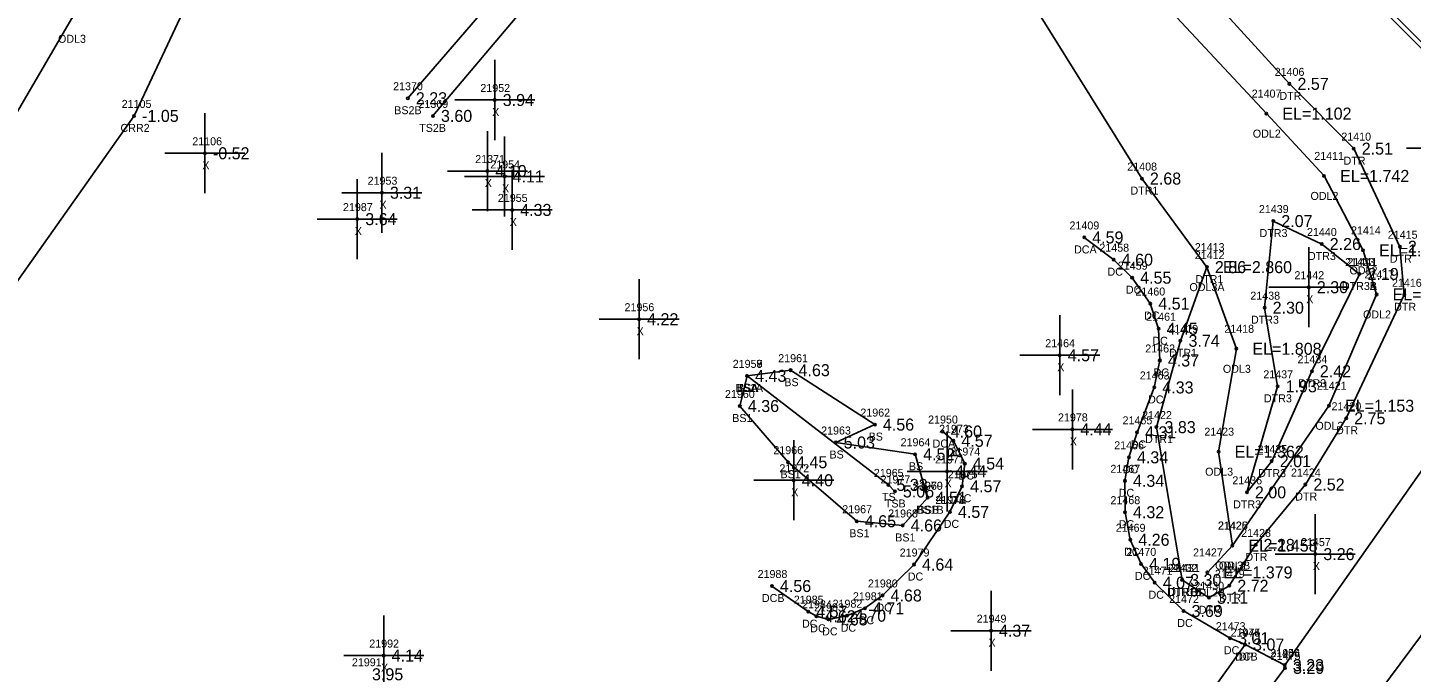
# Model space of a CAD drawing. Extents: x 2608745 to 2610333, y 641917 to 643463.
# Drawn here: x 2609885.8 to 2610058.8, y 642076.5 to 642157.1 of the extents above; entities that cross this region are included whole.
import ezdxf

# ---------------------------------------------------------------- set-up
doc = ezdxf.new("R2010")
doc.units = 0
for name, color, linetype in [('RD_DTM_BkLn1', 7, 'Continuous'), ('RD_DTM_BkLn2', 7, 'Continuous'), ('RD_DTM_BkLn_txCode', 7, 'Continuous'), ('RD_EX_Conc', 7, 'Continuous'), ('RD_EX_Conc_txCode', 7, 'Continuous'), ('RD_EX_Driveway', 7, 'Continuous'), ('RD_EX_Driveway_txCode', 7, 'Continuous'), ('RD_EX_H2O', 7, 'Continuous'), ('RD_EX_H2O_txCode', 7, 'Continuous'), ('RD_EX_Misc', 7, 'Continuous'), ('RD_EX_Misc_txCode', 7, 'Continuous'), ('RD_EX_Road', 7, 'Continuous'), ('RD_EX_Road_txCode', 7, 'Continuous'), ('RD_EX_TX_Conc_ELEV', 7, 'Continuous'), ('RD_EX_TX_Driveway_ELEV', 7, 'Continuous'), ('RD_EX_TX_H2O_ELEV', 7, 'Continuous'), ('RD_EX_TX_Misc_ELEV', 7, 'Continuous'), ('RD_EX_TX_Road_ELEV', 7, 'Continuous'), ('RD_SMD_Locator', 7, 'Continuous')]:
    doc.layers.add(name, color=color, linetype=linetype)

msp = doc.modelspace()

# ---------------------------------------------------------------- linework, layer by layer
at = {"layer": 'RD_DTM_BkLn1'}
for points in [[(2609991.14, 642222.22), (2610004.52, 642209.47), (2610026.41, 642188.23), (2610060.62, 642153.9), (2610064.44, 642147.89), (2610069, 642144.94), (2610070.6, 642141.24), (2610070.91, 642133.58), (2610072.62, 642129.27)], [(2610092.08, 642124.26), (2610033.92, 642046.06), (2609975.15, 641967.52)]]:
    msp.add_lwpolyline(points, dxfattribs=at)
at = {"layer": 'RD_DTM_BkLn2'}
for points in [[(2609957.67, 642238.22), (2609985.77, 642215.29), (2609991.2, 642207.2), (2609988.28, 642202.04), (2609982.8, 642193.37), (2609979.92, 642194.31), (2609971.84, 642180.1), (2609960.45, 642174.49), (2609936.49, 642146.07)], [(2609985.47, 642202.04), (2609967.41, 642183.84), (2609958.63, 642177.64), (2609933.35, 642148.28)], [(2609975.75, 642113.58), (2609974.84, 642109.81), (2609980.87, 642102.79), (2609989.46, 642095.41), (2609995.2, 642094.88), (2609998.3, 642098.34)], [(2609975.75, 642113.58), (2609981.18, 642114.29), (2609991.72, 642107.49), (2609986.82, 642105.25), (2609996.75, 642103.78), (2609998.3, 642098.34)], [(2609975.75, 642113.58), (2609993.41, 642099.95), (2609994.22, 642099.13)]]:
    msp.add_lwpolyline(points, dxfattribs=at)
at = {"layer": 'RD_EX_Conc'}
for points in [[(2610017.88, 642130.88), (2610021.57, 642128.1), (2610023.87, 642125.85), (2610026.14, 642122.62), (2610027.17, 642119.47), (2610027.33, 642115.5), (2610026.64, 642112.13), (2610024.48, 642106.52), (2610023.47, 642103.4), (2610022.97, 642100.46), (2610022.98, 642096.54), (2610023.64, 642093.09), (2610024.99, 642090.08), (2610026.69, 642087.72), (2610030.29, 642084.19), (2610036.11, 642080.79), (2610037.98, 642080)], [(2610000.2, 642106.62), (2610001.53, 642105.46), (2610002.96, 642102.62), (2610002.62, 642099.78), (2610001.1, 642096.58), (2609996.61, 642090), (2609992.68, 642086.13), (2609990.48, 642084.53), (2609988.22, 642083.6), (2609985.91, 642083.14), (2609984.42, 642083.53), (2609983.39, 642084.11), (2609978.85, 642087.31)]]:
    msp.add_lwpolyline(points, dxfattribs=at)
at = {"layer": 'RD_EX_Driveway'}
msp.add_lwpolyline([(2610042.94, 642077.42), (2610037.98, 642080), (2610027.54, 642065.43), (2610017.89, 642052.74), (2610020.81, 642047.62)], dxfattribs=at)
at = {"layer": 'RD_EX_H2O'}
for points in [[(2609545.26, 642628.98), (2609557.91, 642602.6), (2609591.74, 642540.6), (2609658.48, 642494.06), (2609739.9, 642422.86), (2609760.07, 642378.85), (2609808.54, 642339.07), (2609896.37, 642269.89), (2609925.48, 642240.69), (2609915.11, 642188.91), (2609891.33, 642158.21), (2609835.84, 642063.03)], [(2610001.65, 642196), (2609997.03, 642195), (2609993.92, 642192.05), (2609993.23, 642189.36), (2610025.09, 642138.24), (2610033.21, 642127.17), (2610029.91, 642117.96), (2610026.91, 642107.17), (2610030.12, 642088.07)], [(2610001.65, 642196), (2610043.53, 642150.08), (2610051.56, 642141.98), (2610057.33, 642129.72), (2610057.88, 642123.71), (2610050.62, 642108.28), (2610045.52, 642100), (2610039.29, 642092.45), (2610036.01, 642087.34), (2610033.47, 642085.84), (2610030.12, 642088.07)], [(2609998.2, 642191.89), (2610040.64, 642146.36), (2610047.86, 642138.57), (2610052.73, 642129.26), (2610054.42, 642123.75), (2610048.47, 642109.84), (2610036.4, 642092.37), (2610033.27, 642089.01)], [(2609911.25, 642171.95), (2609899.14, 642146.07), (2609837.93, 642059.5)], [(2610052.28, 642126.31), (2610046.33, 642114.16), (2610041.32, 642102.92), (2610038.21, 642099.02), (2610042.05, 642112.27), (2610040.43, 642122.1), (2610041.51, 642132.93), (2610047.56, 642130.06), (2610052.28, 642126.31)], [(2610033.21, 642127.17), (2610036.9, 642116.96), (2610034.68, 642104.1), (2610036.4, 642092.37)]]:
    msp.add_lwpolyline(points, dxfattribs=at)
at = {"layer": 'RD_EX_Misc'}
for p, q in [((2609944.21, 642143.06), (2609944.21, 642153.06)), ((2609907.99, 642136.4), (2609907.99, 642146.4)), ((2609939.21, 642148.06), (2609949.21, 642148.06)), ((2609943.29, 642134.18), (2609943.29, 642144.18)), ((2609945.44, 642133.5), (2609945.44, 642143.5)), ((2609902.99, 642141.4), (2609912.99, 642141.4)), ((2609930.11, 642131.47), (2609930.11, 642141.47)), ((2610058.17, 642142.04), (2610068.17, 642142.04)), ((2609927.03, 642128.17), (2609927.03, 642138.17)), ((2609938.29, 642139.18), (2609948.29, 642139.18)), ((2609940.44, 642138.5), (2609950.44, 642138.5)), ((2609946.39, 642129.32), (2609946.39, 642139.32)), ((2609925.11, 642136.47), (2609935.11, 642136.47)), ((2609941.39, 642134.32), (2609951.39, 642134.32)), ((2609922.03, 642133.17), (2609932.03, 642133.17)), ((2610045.95, 642119.66), (2610045.95, 642129.66)), ((2609962.25, 642115.66), (2609962.25, 642125.66)), ((2610040.95, 642124.66), (2610050.95, 642124.66)), ((2609957.25, 642120.66), (2609967.25, 642120.66)), ((2610014.82, 642111.16), (2610014.82, 642121.16)), ((2610009.82, 642116.16), (2610019.82, 642116.16)), ((2610016.4, 642101.89), (2610016.4, 642111.89)), ((2610000.74, 642096.63), (2610000.74, 642106.63)), ((2610011.4, 642106.89), (2610021.4, 642106.89)), ((2609981.58, 642095.53), (2609981.58, 642105.53)), ((2609995.74, 642101.63), (2610005.74, 642101.63)), ((2609976.58, 642100.53), (2609986.58, 642100.53)), ((2610046.76, 642086.3), (2610046.76, 642096.3)), ((2610041.76, 642091.3), (2610051.76, 642091.3)), ((2610006.23, 642076.73), (2610006.23, 642086.73)), ((2609930.33, 642073.62), (2609930.33, 642083.62)), ((2610001.23, 642081.73), (2610011.23, 642081.73)), ((2609925.33, 642078.62), (2609935.33, 642078.62))]:
    msp.add_line(p, q, dxfattribs=at)
at = {"layer": 'RD_EX_Road'}
for points in [[(2609991.14, 642222.22), (2610004.6, 642209.66), (2610026.66, 642188.37), (2610066.82, 642148.56), (2610069.65, 642145.36), (2610071.05, 642141.53), (2610071.68, 642138.94), (2610071.34, 642133.72), (2610072.62, 642129.27)], [(2610073.96, 642143.05), (2610073.97, 642133.89), (2610072.62, 642129.27), (2610072.13, 642123.73), (2610071.19, 642117.59), (2610042.94, 642077.42), (2610042.98, 642077.08), (2610020.81, 642047.62), (2610010.68, 642034.57), (2609995.36, 642013.51), (2609993.98, 642012.16), (2609992.65, 642010.59), (2609982.73, 641996.33), (2609971.73, 641982.02), (2609971.56, 641981.9), (2609966, 641974.62)]]:
    msp.add_lwpolyline(points, dxfattribs=at)
at = {"layer": 'RD_SMD_Locator'}
for centre in [(2610043.53, 642150.08), (2609933.35, 642148.28), (2609944.21, 642148.06), (2610040.64, 642146.36), (2609899.14, 642146.07), (2609936.49, 642146.07), (2609907.99, 642141.4), (2610051.56, 642141.98), (2609943.29, 642139.18), (2609945.44, 642138.5), (2610025.09, 642138.24), (2610047.86, 642138.57), (2609930.11, 642136.47), (2609946.39, 642134.32), (2609927.03, 642133.17), (2610041.51, 642132.93), (2610017.88, 642130.88), (2610047.56, 642130.06), (2610052.73, 642129.26), (2610057.33, 642129.72), (2610021.57, 642128.1), (2610023.87, 642125.85), (2610033.21, 642127.17), (2610033.21, 642127.17), (2610052.28, 642126.31), (2610052.28, 642126.31), (2610045.95, 642124.66), (2610054.42, 642123.75), (2610026.14, 642122.62), (2610040.43, 642122.1), (2610057.88, 642123.71), (2609962.25, 642120.66), (2610027.17, 642119.47), (2610029.91, 642117.96), (2610036.9, 642116.96), (2610014.82, 642116.16), (2610027.33, 642115.5), (2609975.75, 642113.58), (2609975.75, 642113.58), (2609975.75, 642113.58), (2609981.18, 642114.29), (2610046.33, 642114.16), (2610026.64, 642112.13), (2610042.05, 642112.27), (2609974.84, 642109.81), (2610048.47, 642109.84), (2610050.62, 642108.28), (2609991.72, 642107.49), (2610000.2, 642106.62), (2610016.4, 642106.89), (2610024.48, 642106.52), (2610026.91, 642107.17), (2609986.82, 642105.25), (2610001.53, 642105.46), (2609996.75, 642103.78), (2610023.47, 642103.4), (2610034.68, 642104.1), (2609980.87, 642102.79), (2610000.74, 642101.63), (2610002.96, 642102.62), (2610041.32, 642102.92), (2609981.58, 642100.53), (2609993.41, 642099.95), (2610002.62, 642099.78), (2610022.97, 642100.46), (2610045.52, 642100), (2609994.22, 642099.13), (2609998.3, 642098.34), (2609998.3, 642098.34), (2610038.21, 642099.02), (2610001.1, 642096.58), (2610022.98, 642096.54), (2609989.46, 642095.41), (2609995.2, 642094.88), (2610023.64, 642093.09), (2610036.4, 642092.37), (2610036.4, 642092.37), (2610039.29, 642092.45), (2610046.76, 642091.3), (2609996.61, 642090), (2610024.99, 642090.08), (2610026.69, 642087.72), (2610030.12, 642088.07), (2610030.12, 642088.07), (2610033.27, 642089.01), (2609978.85, 642087.31), (2609992.68, 642086.13), (2610033.47, 642085.84), (2610036.01, 642087.34), (2609983.39, 642084.11), (2609990.48, 642084.53), (2610030.29, 642084.19), (2609984.42, 642083.53), (2609985.91, 642083.14), (2609988.22, 642083.6), (2610006.23, 642081.73), (2610036.11, 642080.79), (2610037.98, 642080), (2610037.98, 642080), (2609930.33, 642078.62), (2610042.94, 642077.42), (2610042.94, 642077.42), (2610042.98, 642077.08)]:
    msp.add_circle(centre, 0.15, dxfattribs=at)

# ---------------------------------------------------------------- texts
at = {"layer": 'RD_DTM_BkLn_txCode'}
for s, p in [('21370', (2609931.51, 642149.28)), ('BS2B', (2609931.65, 642146.28)), ('21369', (2609934.67, 642147.07)), ('TS2B', (2609934.77, 642144.07)), ('21957', (2609973.95, 642114.58)), ('21958', (2609973.95, 642114.58)), ('21959', (2609973.95, 642114.58)), ('21961', (2609979.64, 642115.29)), ('21960', (2609972.98, 642110.81)), ('BS1A', (2609974.31, 642111.58)), ('TSA', (2609974.46, 642111.58)), ('BSA', (2609974.48, 642111.58)), ('BS', (2609980.4, 642112.29)), ('BS1', (2609973.89, 642107.81)), ('21962', (2609989.9, 642108.49)), ('21963', (2609985, 642106.25)), ('BS', (2609990.94, 642105.49)), ('21964', (2609994.93, 642104.78)), ('21966', (2609979.03, 642103.79)), ('BS', (2609986.04, 642103.25)), ('BS1', (2609979.92, 642100.79)), ('21965', (2609991.59, 642100.95)), ('BS', (2609995.97, 642101.78)), ('21977', (2609992.43, 642100.13)), ('21970', (2609996.47, 642099.34)), ('21969', (2609996.49, 642099.34)), ('TS', (2609992.61, 642097.95)), ('TSB', (2609992.96, 642097.13)), ('21967', (2609987.64, 642096.41)), ('21968', (2609993.38, 642095.88)), ('BS1B', (2609996.89, 642096.34)), ('BSB', (2609997.05, 642096.34)), ('BS1', (2609988.52, 642093.41)), ('BS1', (2609994.26, 642092.88)), ('21991', (2609926.36, 642077.28))]:
    msp.add_text(s, height=1, dxfattribs=at).set_placement(p)
at = {"layer": 'RD_EX_Conc_txCode'}
for s, p in [('21409', (2610016.04, 642131.88)), ('DCA', (2610016.61, 642128.88)), ('21458', (2610019.77, 642129.1)), ('21459', (2610022.08, 642126.85)), ('DC', (2610020.79, 642126.1)), ('DC', (2610023.09, 642123.85)), ('21460', (2610024.28, 642123.62)), ('DC', (2610025.36, 642120.62)), ('21461', (2610025.63, 642120.47)), ('21462', (2610025.51, 642116.5)), ('DC', (2610026.39, 642117.47)), ('21463', (2610024.82, 642113.13)), ('DC', (2610026.55, 642113.5)), ('DC', (2610025.86, 642110.13)), ('21950', (2609998.37, 642107.62)), ('21465', (2610022.67, 642107.52)), ('21973', (2609999.74, 642106.46)), ('DCA', (2609998.93, 642104.62)), ('21466', (2610021.63, 642104.4)), ('DC', (2610023.7, 642104.52)), ('DC', (2610000.75, 642103.46)), ('21974', (2610001.16, 642103.62)), ('21975', (2610000.83, 642100.78)), ('DC', (2610002.18, 642100.62)), ('21467', (2610021.15, 642101.46)), ('DC', (2610022.69, 642101.4)), ('21976', (2609999.28, 642097.58)), ('DC', (2610001.84, 642097.78)), ('21468', (2610021.16, 642097.54)), ('DC', (2610022.19, 642098.46)), ('DC', (2610000.32, 642094.58)), ('21469', (2610021.82, 642094.09)), ('DC', (2610022.2, 642094.54)), ('21979', (2609994.82, 642091)), ('DC', (2610022.86, 642091.09)), ('21470', (2610023.16, 642091.08)), ('21988', (2609977.06, 642088.31)), ('21471', (2610025.18, 642088.72)), ('21980', (2609990.85, 642087.13)), ('DC', (2609995.83, 642088)), ('DC', (2610024.21, 642088.08)), ('DCB', (2609977.6, 642085.31)), ('21985', (2609981.59, 642085.11)), ('21981', (2609988.97, 642085.53)), ('DC', (2610025.91, 642085.72)), ('21472', (2610028.49, 642085.19)), ('21984', (2609982.62, 642084.53)), ('21983', (2609984.12, 642084.14)), ('21982', (2609986.43, 642084.6)), ('DC', (2609991.91, 642084.13)), ('DC', (2609982.61, 642082.11)), ('DC', (2609983.64, 642081.53)), ('DC', (2609987.44, 642081.6)), ('DC', (2609989.7, 642082.53)), ('DC', (2610029.51, 642082.19)), ('21473', (2610034.32, 642081.79)), ('DC', (2609985.13, 642081.14)), ('21474', (2610036.18, 642081)), ('DC', (2610035.33, 642078.79)), ('DCB', (2610036.73, 642078))]:
    msp.add_text(s, height=1, dxfattribs=at).set_placement(p)
at = {"layer": 'RD_EX_Driveway_txCode'}
for s, p in [('21945', (2610036.18, 642081)), ('DP', (2610037.2, 642078)), ('21944', (2610041.15, 642078.42))]:
    msp.add_text(s, height=1, dxfattribs=at).set_placement(p)
at = {"layer": 'RD_EX_H2O_txCode'}
for s, p in [('ODL3', (2609889.63, 642155.21)), ('21406', (2610041.68, 642151.08)), ('21407', (2610038.81, 642148.36)), ('DTR', (2610042.27, 642148.08)), ('21105', (2609897.59, 642147.07)), ('CRR2', (2609897.44, 642144.07)), ('ODL2', (2610038.95, 642143.36)), ('21410', (2610050.01, 642142.98)), ('21411', (2610046.63, 642140.57)), ('21408', (2610023.26, 642139.24)), ('DTR', (2610050.29, 642139.98)), ('DTR1', (2610023.66, 642136.24)), ('ODL2', (2610046.16, 642135.57)), ('21439', (2610039.71, 642133.93)), ('DTR3', (2610039.79, 642130.93)), ('21440', (2610045.72, 642131.06)), ('21414', (2610051.22, 642131.26)), ('21415', (2610055.82, 642130.72)), ('21413', (2610031.7, 642129.17)), ('21412', (2610031.7, 642128.17)), ('DTR3', (2610045.84, 642128.06)), ('21433', (2610050.49, 642127.31)), ('21441', (2610050.77, 642127.31)), ('DTR', (2610056.07, 642127.72)), ('DTR1', (2610031.77, 642125.17)), ('ODL2', (2610051.04, 642126.26)), ('21417', (2610052.9, 642125.75)), ('21416', (2610056.34, 642124.71)), ('ODL3A', (2610031.03, 642124.17)), ('21438', (2610038.64, 642123.1)), ('DTR3A', (2610050.08, 642124.31)), ('DTR3B', (2610050.09, 642124.31)), ('DTR', (2610056.61, 642121.71)), ('DTR3', (2610038.72, 642120.1)), ('ODL2', (2610052.72, 642120.75)), ('21419', (2610028.4, 642118.96)), ('21418', (2610035.39, 642118.96)), ('DTR1', (2610028.48, 642115.96)), ('21434', (2610044.54, 642115.16)), ('ODL3', (2610035.21, 642113.96)), ('21437', (2610040.26, 642113.27)), ('DTR3', (2610044.62, 642112.16)), ('21421', (2610046.95, 642111.84)), ('DTR3', (2610040.34, 642110.27)), ('21420', (2610048.79, 642109.28)), ('21422', (2610025.12, 642108.17)), ('21423', (2610032.89, 642106.1)), ('ODL2', (2610046.77, 642106.84)), ('DTR', (2610049.35, 642106.28)), ('DTR1', (2610025.48, 642105.17)), ('21435', (2610039.53, 642103.92)), ('ODL3', (2610032.99, 642101.1)), ('DTR3', (2610039.61, 642100.92)), ('21424', (2610043.72, 642101)), ('21436', (2610036.39, 642100.02)), ('DTR3', (2610036.49, 642097.02)), ('DTR', (2610044.25, 642098)), ('21426', (2610034.58, 642094.37)), ('21425', (2610034.61, 642094.37)), ('21428', (2610037.5, 642093.45)), ('21427', (2610031.48, 642091.01)), ('DTR', (2610038.02, 642090.45)), ('21432', (2610028.33, 642089.07)), ('21431', (2610028.61, 642089.07)), ('21429', (2610034.21, 642088.34)), ('ODL3B', (2610034.24, 642089.37)), ('ODL2', (2610034.71, 642089.37)), ('21430', (2610031.64, 642086.84)), ('DTR1B', (2610028.22, 642086.07)), ('DTRB', (2610028.38, 642086.07)), ('ODL2B', (2610031.11, 642086.01)), ('DTR', (2610034.74, 642085.34)), ('DTR', (2610032.2, 642083.84))]:
    msp.add_text(s, height=1, dxfattribs=at).set_placement(p)
at = {"layer": 'RD_EX_Misc_txCode'}
for s, p in [('21952', (2609942.41, 642149.06)), ('X', (2609943.89, 642146.06)), ('21106', (2609906.41, 642142.4)), ('21371', (2609941.77, 642140.18)), ('X', (2609907.67, 642139.4)), ('21954', (2609943.65, 642139.5)), ('21953', (2609928.32, 642137.47)), ('X', (2609942.97, 642137.18)), ('21955', (2609944.6, 642135.32)), ('X', (2609945.13, 642136.5)), ('21987', (2609925.24, 642134.17)), ('X', (2609929.8, 642134.47)), ('X', (2609946.08, 642132.32)), ('X', (2609926.72, 642131.17)), ('21442', (2610044.15, 642125.66)), ('21956', (2609960.43, 642121.66)), ('X', (2610045.63, 642122.66)), ('X', (2609961.94, 642118.66)), ('21464', (2610013.01, 642117.16)), ('X', (2610014.51, 642114.16)), ('21978', (2610014.6, 642107.89)), ('X', (2610016.08, 642104.89)), ('21971', (2609999.23, 642102.63)), ('21972', (2609979.79, 642101.53)), ('X', (2610000.43, 642099.63)), ('X', (2609981.27, 642098.53)), ('21457', (2610044.97, 642092.3)), ('X', (2610046.45, 642089.3)), ('21949', (2610004.44, 642082.73)), ('X', (2610005.92, 642079.73)), ('21992', (2609928.53, 642079.62)), ('X', (2609930.01, 642076.62))]:
    msp.add_text(s, height=1, dxfattribs=at).set_placement(p)
at = {"layer": 'RD_EX_Road_txCode'}
for s, p in [('21456', (2610041.12, 642078.42)), ('21475', (2610041.19, 642078.08))]:
    msp.add_text(s, height=1, dxfattribs=at).set_placement(p)
at = {"layer": 'RD_EX_TX_Conc_ELEV'}
for s, p in [('4.59', (2610018.88, 642130.13)), ('4.60', (2610022.57, 642127.35)), ('4.55', (2610024.87, 642125.1)), ('4.51', (2610027.14, 642121.87)), ('4.45', (2610028.17, 642118.72)), ('4.37', (2610028.33, 642114.75)), ('4.33', (2610027.64, 642111.38)), ('4.60', (2610001.2, 642105.87)), ('4.31', (2610025.48, 642105.77)), ('4.57', (2610002.53, 642104.71)), ('4.54', (2610003.96, 642101.87)), ('4.34', (2610024.47, 642102.65)), ('4.57', (2610003.62, 642099.03)), ('4.34', (2610023.97, 642099.71)), ('4.57', (2610002.1, 642095.83)), ('4.32', (2610023.98, 642095.79)), ('4.26', (2610024.64, 642092.34)), ('4.64', (2609997.61, 642089.25)), ('4.19', (2610025.99, 642089.33)), ('4.56', (2609979.85, 642086.56)), ('4.07', (2610027.69, 642086.97)), ('4.68', (2609993.68, 642085.38)), ('4.57', (2609984.39, 642083.36)), ('4.62', (2609985.42, 642082.78)), ('4.70', (2609989.22, 642082.85)), ('4.71', (2609991.48, 642083.78)), ('3.69', (2610031.29, 642083.44)), ('4.63', (2609986.91, 642082.39)), ('3.01', (2610037.11, 642080.04)), ('3.07', (2610038.98, 642079.25))]:
    msp.add_text(s, height=1.5, dxfattribs=at).set_placement(p)
at = {"layer": 'RD_EX_TX_Driveway_ELEV'}
for s, p in [('3.07', (2610038.98, 642079.25)), ('3.23', (2610043.94, 642076.67))]:
    msp.add_text(s, height=1.5, dxfattribs=at).set_placement(p)
at = {"layer": 'RD_EX_TX_H2O_ELEV'}
for s, p in [('2.57', (2610044.53, 642149.33)), ('-1.05', (2609900.14, 642145.32)), ('EL=1.102', (2610042.64, 642145.61)), ('2.51', (2610052.56, 642141.23)), ('2.68', (2610026.09, 642137.49)), ('EL=1.742', (2610049.86, 642137.82)), ('2.07', (2610042.51, 642132.18)), ('2.26', (2610048.56, 642129.31)), ('EL=1.959', (2610054.73, 642128.51)), ('2.57', (2610058.33, 642128.97)), ('2.86', (2610034.21, 642126.42)), ('EL=2.860', (2610035.21, 642126.42)), ('2.19', (2610053.28, 642125.56)), ('2.19', (2610053.28, 642125.56)), ('EL=0.936', (2610056.42, 642123)), ('2.30', (2610041.43, 642121.35)), ('3.74', (2610030.91, 642117.21)), ('EL=1.808', (2610038.9, 642116.21)), ('2.42', (2610047.33, 642113.41)), ('1.93', (2610043.05, 642111.52)), ('EL=1.153', (2610050.47, 642109.09)), ('2.75', (2610051.62, 642107.53)), ('3.83', (2610027.91, 642106.42)), ('EL=1.362', (2610036.68, 642103.35)), ('2.01', (2610042.32, 642102.17)), ('2.00', (2610039.21, 642098.27)), ('2.52', (2610046.52, 642099.25)), ('EL=1.458', (2610038.4, 642091.62)), ('EL=1.458', (2610038.4, 642091.62)), ('2.28', (2610040.29, 642091.7)), ('EL=1.379', (2610035.27, 642088.26)), ('3.30', (2610031.12, 642087.32)), ('3.30', (2610031.12, 642087.32)), ('2.72', (2610037.01, 642086.59)), ('3.11', (2610034.47, 642085.09))]:
    msp.add_text(s, height=1.5, dxfattribs=at).set_placement(p)
at = {"layer": 'RD_EX_TX_Misc_ELEV'}
for s, p in [('2.23', (2609934.35, 642147.53)), ('3.94', (2609945.21, 642147.31)), ('3.60', (2609937.49, 642145.32)), ('-0.52', (2609908.99, 642140.65)), ('4.10', (2609944.29, 642138.43)), ('4.11', (2609946.44, 642137.75)), ('3.31', (2609931.11, 642135.72)), ('4.33', (2609947.39, 642133.57)), ('3.64', (2609928.03, 642132.42)), ('2.30', (2610046.95, 642123.91)), ('4.22', (2609963.25, 642119.91)), ('4.57', (2610015.82, 642115.41)), ('4.43', (2609976.75, 642112.83)), ('4.43', (2609976.75, 642112.83)), ('4.43', (2609976.75, 642112.83)), ('4.63', (2609982.18, 642113.54)), ('4.36', (2609975.84, 642109.06)), ('4.56', (2609992.72, 642106.74)), ('4.44', (2610017.4, 642106.14)), ('5.03', (2609987.82, 642104.5)), ('4.45', (2609981.87, 642102.04)), ('4.52', (2609997.75, 642103.03)), ('4.44', (2610001.74, 642100.88)), ('4.40', (2609982.58, 642099.78)), ('5.33', (2609994.41, 642099.2)), ('5.06', (2609995.22, 642098.38)), ('4.51', (2609999.3, 642097.59)), ('4.51', (2609999.3, 642097.59)), ('4.65', (2609990.46, 642094.66)), ('4.66', (2609996.2, 642094.13)), ('3.26', (2610047.76, 642090.55)), ('4.37', (2610007.23, 642080.98)), ('4.14', (2609931.33, 642077.87)), ('3.95', (2609928.87, 642075.53))]:
    msp.add_text(s, height=1.5, dxfattribs=at).set_placement(p)
at = {"layer": 'RD_EX_TX_Road_ELEV'}
for s, p in [('3.23', (2610043.94, 642076.67)), ('3.29', (2610043.98, 642076.33))]:
    msp.add_text(s, height=1.5, dxfattribs=at).set_placement(p)

doc.saveas('drawing.dxf')
